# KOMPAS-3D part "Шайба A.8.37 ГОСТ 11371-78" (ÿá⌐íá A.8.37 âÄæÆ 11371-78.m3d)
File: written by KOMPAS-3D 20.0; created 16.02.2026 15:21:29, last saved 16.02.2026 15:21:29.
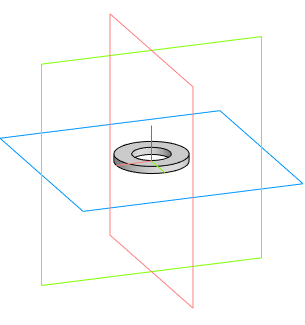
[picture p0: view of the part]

Document properties: Автор: admin; Полное имя файла: P:\INSTART\Технический отдел\ОР\Прочие задачи\КД на номенклатурный ряд\КД на типоразмеры дросселей\Сетевые дроссели ISF\ISF-4\Тип 1\ISF-132_256-4\0723\Новая папка\Шайба A.8.37 ГОСТ 11371-78.m3d

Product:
- Part/product: Шайба A.8.37 ГОСТ 11371-78

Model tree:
1. Операция без истории:1  (labels: Шайба A.8.37 ГОСТ 11371-78)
